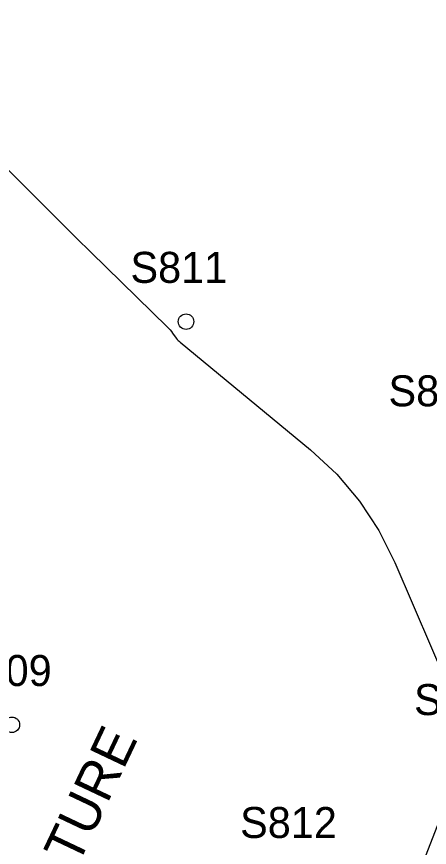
# Model space of a CAD drawing. Extents: x 816928 to 825690, y 436959 to 448212.
# Drawn here: x 818686.8 to 818740.2, y 444730.2 to 444837.4 of the extents above; entities that cross this region are included whole.
import ezdxf

# ---------------------------------------------------------------- set-up
doc = ezdxf.new("R2010")
doc.units = 0
for name, color, linetype in [('SURVEY - CONTOURS - Intermediate with optional Text', 7, 'Continuous'), ('SURVEY - DTM - Spot Points - Locators', 7, 'Continuous'), ('SURVEY - DTM - Spot Points - Point Numbers', 7, 'Continuous'), ('SURVEY - NON-TRANSPORTATION - Features - Points - Numbers', 7, 'Continuous'), ('SURVEY - NON-TRANSPORTATION - Features Text', 7, 'Continuous'), ('SURVEY - PROPERTY - Parcels', 7, 'Continuous'), ('SURVEY - PROPERTY - ROW Lines', 7, 'Continuous')]:
    doc.layers.add(name, color=color, linetype=linetype)

msp = doc.modelspace()

# ---------------------------------------------------------------- linework, layer by layer
at = {"layer": 'SURVEY - CONTOURS - Intermediate with optional Text'}
msp.add_lwpolyline([(818680.68, 444822.72), (818689.15, 444814.28), (818690.96, 444812.47), (818692.78, 444810.66), (818694.6, 444808.87), (818696.43, 444807.07), (818706.32, 444797.39), (818706.5, 444797.21), (818706.67, 444797.02), (818706.83, 444796.82), (818706.98, 444796.62), (818707.47, 444795.94), (818707.57, 444795.8), (818707.69, 444795.67), (818707.82, 444795.55), (818707.95, 444795.43), (818724.8, 444781.54), (818728.19, 444778.4), (818731.13, 444774.93), (818733.64, 444771.12), (818735.7, 444766.99), (818742.77, 444750.5)], dxfattribs=at)
at = {"layer": 'SURVEY - DTM - Spot Points - Locators'}
for centre in [(818708.73, 444798.09), (818686.24, 444746.07)]:
    msp.add_circle(centre, 1, dxfattribs=at)
at = {"layer": 'SURVEY - PROPERTY - Parcels'}
msp.add_line((818717.18, 444671.42), (818795.05, 444871.45), dxfattribs=at)
at = {"layer": 'SURVEY - PROPERTY - ROW Lines'}
msp.add_line((818717.18, 444671.42), (818850.08, 445012.81), dxfattribs=at)

# ---------------------------------------------------------------- texts
at = {"layer": 'SURVEY - DTM - Spot Points - Point Numbers'}
for s, p in [('S811', (818701.55, 444803.09)), ('S815', (818734.87, 444787.16)), ('S809', (818678.89, 444751.07)), ('S812', (818715.71, 444731.46))]:
    msp.add_text(s, height=4, dxfattribs=at).set_placement(p)
at = {"layer": 'SURVEY - NON-TRANSPORTATION - Features - Points - Numbers'}
msp.add_text('S206', height=4, dxfattribs=at).set_placement((818738.17, 444747.32))
at = {"layer": 'SURVEY - NON-TRANSPORTATION - Features Text'}
msp.add_text('PASTURE', height=5, rotation=64.6538, dxfattribs=at).set_placement((818689.02, 444715.67))

doc.saveas('drawing.dxf')
